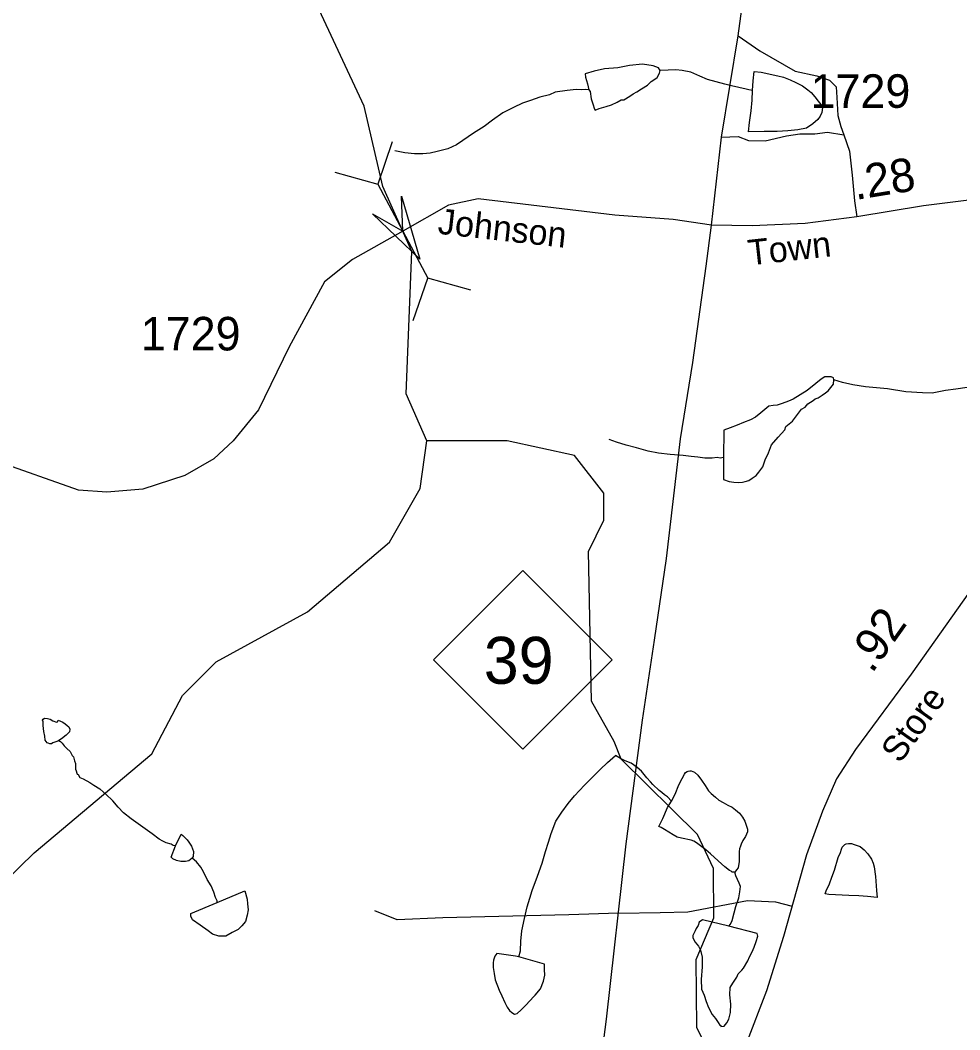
# Model space of a CAD drawing. Extents: x 2126262 to 2293712, y 749403 to 919119.
# Drawn here: x 2215565 to 2219067, y 786501 to 790264 of the extents above; entities that cross this region are included whole.
import ezdxf

# ---------------------------------------------------------------- set-up
doc = ezdxf.new("R2010")
doc.units = 0
for name, color, linetype in [('Exist Hydrographic Creek Single Shore', 7, 'Continuous'), ('Exist Hydrographic Misc Water Feature', 7, 'Continuous'), ('Exist Road Non-System Type 51', 7, 'Continuous'), ('Exist Road Primary NC Attributed', 7, 'Continuous'), ('Exist Road Primary NC Shield CELL', 7, 'Continuous'), ('Exist Road Primary NC Shield Number Label', 7, 'Continuous'), ('Exist Road Secondary Mileage Hundredths English Label', 7, 'Continuous'), ('Exist Road Secondary Structure Pipe CELL', 7, 'Continuous'), ('Exist Road Secondary Structure Standard Bridge Attributed CELL', 7, 'Continuous'), ('Exist Road Secondary Type 51 Attributed', 7, 'Continuous'), ('Exist Road Secondary Type 51 Label', 7, 'Continuous'), ('Exist Road Secondary Type 51 Number Label', 7, 'Continuous')]:
    doc.layers.add(name, color=color, linetype=linetype)

msp = doc.modelspace()

# ---------------------------------------------------------------- linework, layer by layer
at = {"layer": 'Exist Hydrographic Creek Single Shore'}
for points in [[(2217080.2, 788695.4), (2217004.1, 788870.8), (2217025.2, 789401.8), (2216916.1, 789643.5), (2216847.2, 789943.5), (2216661.3, 790340.9), (2216626.2, 790531.9), (2216621.3, 791283.1)], [(2217779.2, 787575.6), (2217695.1, 787725), (2217683.2, 788282.8), (2217740.2, 788399.7), (2217740.2, 788501.4), (2217631.2, 788641.4), (2217380.2, 788695.8), (2217080.2, 788695.4)]]:
    msp.add_lwpolyline(points, dxfattribs=at)
at = {"layer": 'Exist Hydrographic Misc Water Feature'}
for points in [[(2217950.6, 790075.7), (2217944.6, 790085.6), (2217924.5, 790093.5), (2217884.5, 790099.2), (2217836.6, 790094.8), (2217792.5, 790086.5), (2217742.7, 790082.2), (2217704.5, 790074), (2217670.9, 790063.7), (2217672.7, 790051.7), (2217679.1, 790025.8), (2217685, 790003.9)], [(2217685, 790003.9), (2217689.3, 789997.9), (2217693.2, 789969.9), (2217699.6, 789952), (2217705.5, 789932), (2217707.8, 789928), (2217723.6, 789934.2), (2217749.6, 789942.3), (2217769.5, 789948.5), (2217789.6, 789958.6), (2217805.4, 789966.7), (2217815.2, 789966.7), (2217837.4, 789980.9), (2217849.3, 789989), (2217863, 789997.1), (2217881.1, 790007.2), (2217903, 790021.3), (2217916.7, 790035.4), (2217930.9, 790043.5), (2217938.9, 790049.6), (2217948.5, 790065.7), (2217950.6, 790075.7)], [(2218295.1, 790002.1), (2218281.1, 790004), (2218270.9, 790005.9), (2218216.7, 790019.5), (2218190.9, 790025.3), (2218126.9, 790042.9), (2218098.6, 790054.7), (2218064.6, 790070.4), (2218032.6, 790076.2), (2218008.6, 790078), (2217980.5, 790077.9), (2217950.6, 790075.7)], [(2218295.1, 790002.1), (2218296.9, 790038), (2218300.6, 790072), (2218326.6, 790070.2), (2218388.6, 790056.7), (2218410.5, 790050.9), (2218434.5, 790041), (2218456.6, 790031.2), (2218480.8, 790019.3), (2218500.7, 790003.5), (2218512.8, 789993.6), (2218527, 789977.7), (2218539.1, 789961.7), (2218549.3, 789949.8), (2218555.3, 789937.9), (2218553.2, 789919.9), (2218547.5, 789905.8), (2218537.6, 789893.8), (2218519.8, 789877.7), (2218495.8, 789861.5), (2218463.8, 789855.3), (2218426.1, 789851), (2218386.1, 789848.7), (2218338.1, 789848.4), (2218280.1, 789848), (2218283.8, 789882.1), (2218289.5, 789926), (2218293.4, 789966), (2218295.1, 790002.1)], [(2217685, 790003.9), (2217671.1, 790005.8), (2217659, 790003.6), (2217637.1, 790005.5), (2217603.4, 790001.3), (2217559.3, 789995), (2217537.4, 789984.8), (2217501.3, 789976.6), (2217467.7, 789964.3), (2217437.5, 789954.2), (2217403.9, 789937.9), (2217363.9, 789917.7), (2217326, 789891.4), (2217294.4, 789867.2), (2217254.6, 789842.9), (2217214.6, 789814.6), (2217190.9, 789798.5), (2217158.9, 789784.3), (2217119.1, 789774), (2217093, 789767.8), (2217065.2, 789765.6), (2217035, 789765.5), (2216999.1, 789769.2), (2216961, 789776.9)], [(2218598.3, 788922.6), (2218596.3, 788930.6), (2218588.3, 788934.5), (2218578.2, 788934.4), (2218564.3, 788934.3), (2218550.4, 788926.2), (2218530.3, 788910.1), (2218498.5, 788883.9), (2218446.8, 788851.6), (2218428.8, 788843.4), (2218405, 788835.2), (2218387.1, 788829.2), (2218371.1, 788827.1), (2218355.1, 788824.9), (2218341, 788812.9), (2218325.4, 788800.7), (2218305.3, 788784.6), (2218287.3, 788774.5), (2218261.6, 788764.3), (2218237.6, 788754.2), (2218211.6, 788744), (2218187.8, 788735.8), (2218186.4, 788633.9)], [(2218186.4, 788633.9), (2218187, 788551.8), (2218207.1, 788544), (2218225.1, 788542.1), (2218243, 788540.2), (2218257.1, 788542.3), (2218267, 788544.4), (2218281.1, 788548.5), (2218292.8, 788556.6), (2218308.8, 788566.7), (2218318.8, 788578.8), (2218332.6, 788598.8), (2218342.2, 788624.9), (2218354.3, 788651), (2218366, 788681), (2218389.8, 788709.2), (2218415.6, 788737.3), (2218419.5, 788749.4), (2218443.3, 788769.5), (2218477.1, 788813.8), (2218491.1, 788821.8), (2218500.7, 788833.9), (2218520.8, 788846), (2218528.8, 788852.1), (2218538.9, 788856.2), (2218554.7, 788866.3), (2218566.6, 788874.4), (2218576.6, 788882.4), (2218586.6, 788894.5), (2218596.3, 788906.5), (2218598.3, 788922.6)], [(2219094.4, 788894), (2219052.3, 788887.8), (2219014.4, 788883.4), (2218964.6, 788873.1), (2218928.5, 788874.8), (2218866.5, 788878.4), (2218798.3, 788890), (2218716.2, 788897.3), (2218668.3, 788905), (2218630.3, 788912.8), (2218598.3, 788922.6)], [(2214355.2, 785277.7), (2214495.1, 785570), (2214808.2, 786045.8), (2214839.1, 786287.9), (2214971.2, 786531.2), (2215137.1, 786632.8), (2215393.2, 786942.4), (2215617.1, 787160.9), (2216056.1, 787529.1), (2216170.1, 787746.5), (2216295.2, 787871.9), (2216635.2, 788058.4), (2216941.1, 788317.8), (2217056.2, 788518.8), (2217080.2, 788695.4)], [(2218186.4, 788633.9), (2218174.5, 788631.7), (2218162.4, 788633.6), (2218144.6, 788631.5), (2218116.5, 788631.3), (2218090.6, 788635.1), (2218066.6, 788637), (2218036.3, 788640.8), (2217988.3, 788644.5), (2217944.2, 788650.2), (2217906.3, 788657.9), (2217862.4, 788669.6), (2217824.3, 788679.3), (2217788, 788691), (2217760.1, 788700.9)], [(2215708.5, 787579.1), (2215704.6, 787577.1), (2215686.8, 787570.9), (2215680.9, 787566.9), (2215674.9, 787566.9), (2215668.8, 787568.8), (2215664.9, 787570.8), (2215658.5, 787580.8), (2215656.7, 787594.7), (2215652.6, 787612.7), (2215650.3, 787634.7), (2215650.3, 787640.7), (2215650.3, 787648.7), (2215648, 787654.7), (2215650.1, 787658.7), (2215656, 787662.7), (2215666.1, 787660.8), (2215676.1, 787658.9), (2215686, 787652.9), (2215700.1, 787647), (2215704, 787649), (2215706.1, 787655), (2215724.1, 787647.2), (2215732.3, 787641.2), (2215740.3, 787635.3), (2215746.3, 787629.4), (2215750.4, 787621.4), (2215748.3, 787611.4), (2215736.6, 787599.3), (2215718.6, 787585.2), (2215708.5, 787579.1)], [(2215708.5, 787579.1), (2215714.5, 787575.1), (2215720.8, 787569.2), (2215728.8, 787559.2), (2215738.9, 787549.3), (2215750.8, 787537.4), (2215759, 787523.5), (2215763.1, 787517.5), (2215767, 787503.6), (2215771.3, 787493.6), (2215771.3, 787479.6), (2215771.3, 787471.6), (2215773.3, 787465.6), (2215775.6, 787457.6), (2215777.6, 787453.6), (2215781.5, 787451.7), (2215787.5, 787441.7), (2215799.6, 787435.8), (2215823.8, 787421.9), (2215839.8, 787412), (2215861.7, 787398.3), (2215875.9, 787386.3), (2215890, 787372.4), (2215904.2, 787360.5)], [(2218497, 784966.2), (2218211.2, 785378.8), (2218202.2, 785497.1), (2218160.2, 785612.7), (2218240.1, 786037.5), (2218205.1, 786271.1), (2218087.2, 786509.8), (2218085.1, 786762.4), (2218150.1, 786918.4), (2218149.1, 787102.2), (2218090.2, 787228.1), (2217805.2, 787509.4), (2217779.2, 787575.6)], [(2217423.6, 786773.3), (2217429.3, 786795.3), (2217431, 786831.3), (2217434.9, 786869.3), (2217444.5, 786915.3), (2217454.3, 786959.4), (2217464, 786991.4), (2217473.8, 787019.5), (2217493.5, 787073.6), (2217511.1, 787121.7), (2217522.8, 787165.8), (2217534.5, 787199.9), (2217544.4, 787232), (2217562, 787278), (2217583.7, 787312.1), (2217607.5, 787344.3), (2217631.3, 787372.5), (2217669, 787412.7), (2217698.8, 787442.9), (2217726.5, 787471.1), (2217754.3, 787497.2), (2217784.3, 787523.4)], [(2217993.2, 787352.9), (2217977.2, 787368.8), (2217967, 787376.8), (2217957.1, 787384.7), (2217947.1, 787392.6), (2217922.9, 787414.5), (2217914.9, 787424.4), (2217900.7, 787440.3), (2217880.7, 787464.1), (2217864.5, 787478), (2217842.3, 787493.9), (2217820.4, 787503.7), (2217802.3, 787511.6), (2217790.2, 787519.5), (2217784.3, 787523.4)], [(2217993.2, 787352.9), (2217997.3, 787361), (2218009, 787385.1), (2218017, 787407.1), (2218022.8, 787419.1), (2218032.8, 787437.2), (2218040.6, 787453.3), (2218044.5, 787459.3), (2218050.6, 787463.3), (2218054.5, 787465.3), (2218060.5, 787465.4), (2218066.6, 787465.5), (2218072.6, 787463.5), (2218078.5, 787461.5), (2218090.6, 787449.6), (2218104.8, 787431.7), (2218118.7, 787411.8), (2218131, 787391.9), (2218141.1, 787382), (2218157.1, 787368.1), (2218169.4, 787356.2), (2218185.4, 787348.3), (2218203.2, 787338.4), (2218219.4, 787330.5), (2218231.5, 787320.6), (2218245.6, 787308.7), (2218257.5, 787292.8), (2218265.7, 787278.9), (2218275.8, 787249), (2218276, 787239), (2218268, 787220.9), (2218258.4, 787206.8), (2218252.2, 787192.8), (2218250.4, 787184.8), (2218246.5, 787174.8), (2218244.6, 787164.8), (2218244.6, 787158.8), (2218244.6, 787142.8), (2218244.8, 787126.8), (2218242.8, 787112.8), (2218241.1, 787104.8), (2218235, 787096.8), (2218233.1, 787092.7), (2218229, 787088.7)], [(2216143.2, 787186.2), (2216135, 787188.2), (2216127, 787192.1), (2216109, 787198), (2216097.1, 787203.9), (2216083, 787211.8), (2216056.7, 787231.6), (2215978.6, 787287.1), (2215950.3, 787308.9), (2215930.4, 787330.7), (2215910.1, 787354.5), (2215904.2, 787360.5)], [(2218229, 787088.7), (2218223.1, 787088.6), (2218219, 787088.6), (2218215.1, 787092.6), (2218209.1, 787094.6), (2218191.1, 787108.5), (2218166.7, 787130.3), (2218138.6, 787156.1), (2218120.6, 787171.9), (2218086.3, 787197.7), (2218076.3, 787203.6), (2218066.2, 787207.5), (2218030.3, 787215.2), (2218014.3, 787219.1), (2217998.4, 787227.1), (2217966, 787246.8), (2217954.1, 787254.8), (2217946.1, 787258.7), (2217959.8, 787288.8), (2217977.6, 787328.9), (2217993.2, 787352.9)], [(2216143.2, 787186.2), (2216164.8, 787230.4), (2216170.7, 787224.4), (2216181, 787214.5), (2216187.1, 787208.5), (2216193.1, 787200.6), (2216203.1, 787184.7), (2216207.2, 787174.7), (2216211.3, 787164.8), (2216211.3, 787158.8), (2216209.3, 787152.8), (2216209.5, 787146.8), (2216205.6, 787140.7)], [(2216205.6, 787140.7), (2216193.5, 787130.6), (2216181.6, 787128.6), (2216163.5, 787128.4), (2216147.6, 787132.3), (2216133.6, 787138.2), (2216127.5, 787144.2), (2216143.2, 787186.2)], [(2218614.5, 787143.3), (2218622.3, 787161.4), (2218626.2, 787173.4), (2218628.3, 787181.4), (2218638.3, 787191.5), (2218644.1, 787193.5), (2218652.1, 787195.6), (2218664, 787195.7), (2218674, 787191.7), (2218696.4, 787183.9), (2218710.3, 787172), (2218724.2, 787156.1), (2218738.6, 787136.2), (2218744.5, 787122.3), (2218748.8, 787108.3), (2218752.9, 787072.3), (2218757.3, 787020.4), (2218759.5, 786994.4), (2218723.6, 786998.1), (2218691.6, 786999.9), (2218653.5, 787001.6), (2218579.5, 787005.2), (2218565.5, 787007.1), (2218569.2, 787019.1), (2218581.3, 787045.2), (2218591, 787069.2), (2218600.8, 787095.3), (2218614.5, 787143.3)], [(2216298.5, 786975.4), (2216298.5, 786981.4), (2216292.5, 786993.4), (2216286.4, 787013.3), (2216276.1, 787037.3), (2216262, 787061.1), (2216247.8, 787089), (2216237.8, 787106.9), (2216221.6, 787126.8), (2216205.6, 787140.7)], [(2218206.5, 786886.7), (2218212.2, 786894.6), (2218218.4, 786908.7), (2218226, 786936.8), (2218232.1, 786960.8), (2218243.8, 786992.8), (2218247.5, 787014.8), (2218249.3, 787034.9), (2218245.2, 787046.8), (2218233.1, 787074.7), (2218229, 787088.7)], [(2216298.5, 786975.4), (2216402.2, 787018.1), (2216410.6, 786988.2), (2216412.5, 786970.2), (2216414.7, 786948.2), (2216410.8, 786928.2), (2216405.1, 786904.2), (2216391.2, 786888), (2216377.2, 786874), (2216355.3, 786863.8), (2216331.5, 786849.7), (2216305.6, 786849.5), (2216281.2, 786857.3), (2216265.3, 786869.2), (2216235.3, 786891), (2216207, 786910.8), (2216201.1, 786924.7), (2216200.9, 786934.7), (2216298.5, 786975.4)], [(2218206.5, 786886.7), (2218108.3, 786910), (2218096.4, 786901.8), (2218092.5, 786889.8), (2218084.5, 786877.8), (2218080.6, 786869.8), (2218072.8, 786851.7), (2218072.8, 786843.7), (2218080.8, 786827.8), (2218093.1, 786811.9), (2218101.1, 786798), (2218107.2, 786771.9), (2218107.6, 786736), (2218103.7, 786688), (2218104, 786652), (2218114.2, 786630.1), (2218122.2, 786606.1), (2218130.6, 786584.2), (2218144.8, 786558.3), (2218156.9, 786542.4), (2218167.1, 786528.5), (2218173.1, 786518.5), (2218177, 786516.6)], [(2218177, 786516.6), (2218177.2, 786512.5), (2218189.1, 786514.6), (2218199.1, 786526.7), (2218206.9, 786540.8), (2218212.6, 786564.8), (2218214.5, 786596.8), (2218210.4, 786630.7), (2218212, 786658.8), (2218221.9, 786674.8), (2218235.8, 786696.9), (2218241.5, 786709), (2218255.5, 786723), (2218261.6, 786731.1), (2218277.2, 786757.2), (2218283.4, 786773.2), (2218293, 786791.3), (2218301, 786809.3), (2218308.8, 786829.3), (2218314.5, 786849.4), (2218312.5, 786859.4), (2218206.5, 786886.7)], [(2217423.6, 786773.3), (2217411.5, 786775.2), (2217341.6, 786784.7), (2217333.6, 786774.6), (2217329.5, 786760.6), (2217327.8, 786750.7), (2217327.8, 786732.6), (2217332.1, 786710.6), (2217336, 786686.7), (2217350.4, 786648.8), (2217360.6, 786626.9), (2217370.9, 786603), (2217380.7, 786585), (2217389.1, 786573.1), (2217397.1, 786565.1), (2217407, 786559.2), (2217417, 786561.3), (2217432.8, 786575.4), (2217448.8, 786591.5), (2217466.4, 786609.6), (2217478.5, 786623.7), (2217484.5, 786629.8), (2217504.4, 786653.9), (2217516.1, 786682), (2217520, 786704), (2217519.8, 786725.9), (2217519.8, 786745.9), (2217423.6, 786773.3)]]:
    msp.add_lwpolyline(points, dxfattribs=at)
at = {"layer": 'Exist Road Non-System Type 51'}
for points in [[(2218241.5, 790205.8), (2218321.9, 790149), (2218453.1, 790073.5), (2218534.1, 790056.8), (2218581.5, 790040), (2218606.6, 790014.9), (2218609.4, 789975.7), (2218612.2, 789908.7), (2218623.4, 789866.8), (2218634.5, 789836.1)], [(2218179.4, 789827.9), (2218241.7, 789829.8), (2218279.4, 789815.8), (2218342.2, 789814.4), (2218421.7, 789832.6), (2218470.6, 789839.6), (2218526.4, 789839.6), (2218573.8, 789846.5), (2218634.5, 789836.1)], [(2218634.5, 789836.1), (2218656.2, 789775.3), (2218665.9, 789685.9), (2218674.3, 789590.9), (2218684.1, 789530.9)], [(2217794.9, 786935.8), (2217950, 786938.1), (2218053.3, 786940.9), (2218276.6, 786982.8), (2218379.8, 786977.2), (2218441.9, 786961.1)], [(2217794.9, 786935.8), (2217609.4, 786929.7), (2217140.5, 786918.5), (2216970.2, 786910.1), (2216886.5, 786943.7)]]:
    msp.add_lwpolyline(points, dxfattribs=at)
at = {"layer": 'Exist Road Primary NC Attributed'}
for points in [[(2218141.2, 789499.3), (2218179.4, 789827.9), (2218241.5, 790205.8), (2218293.9, 790590.6), (2218353.2, 791043.9), (2218383.9, 791246.4), (2218420.9, 791516.7), (2218481.6, 792023), (2218509.5, 792239.6), (2218535.1, 792454.9)], [(2217547.2, 785067.5), (2217573, 785245.6), (2217632.3, 785691.9), (2217656.1, 785859.5), (2217681.2, 786049.5), (2217716.8, 786280.7), (2217750.3, 786540.5), (2217823.5, 787193.5), (2217884.2, 787655.1), (2217929.6, 787953.4), (2217974.3, 788257.9), (2218025.9, 788703.5), (2218072.6, 788987.7), (2218121.5, 789346.7), (2218141.2, 789499.3)]]:
    msp.add_lwpolyline(points, dxfattribs=at)
at = {"layer": 'Exist Road Primary NC Shield CELL'}
msp.add_lwpolyline([(2217105.8, 787880), (2217438.8, 788213), (2217771.8, 787880), (2217438.8, 787547)], close=True, dxfattribs=at)
at = {"layer": 'Exist Road Secondary Structure Pipe CELL'}
for p, q in [((2216951.9, 789810.6), (2216898.5, 789652.8)), ((2216738, 789697.6), (2216898.5, 789652.8)), ((2216898.5, 789652.8), (2217083.8, 789302)), ((2217030.3, 789144.2), (2217083.8, 789302)), ((2217244.2, 789257.2), (2217083.8, 789302))]:
    msp.add_line(p, q, dxfattribs=at)
at = {"layer": 'Exist Road Secondary Structure Standard Bridge Attributed CELL'}
msp.add_lwpolyline([(2216986.7, 789607.3), (2217054, 789372.9), (2216878.5, 789542.2), (2216991.1, 789477.4)], close=True, dxfattribs=at)
at = {"layer": 'Exist Road Secondary Type 51 Attributed'}
for points in [[(2218141.2, 789499.3), (2217999.2, 789521.3), (2217781.5, 789536.7), (2217271.4, 789597.4), (2217161.1, 789573.7), (2216991.1, 789477.4)], [(2219634.1, 789626.5), (2219392.6, 789619.5), (2219140.7, 789597.9), (2218932.7, 789571.3), (2218684.1, 789530.9), (2218491, 789506.4), (2218292.8, 789496.6), (2218141.2, 789499.3)], [(2216991.1, 789477.4), (2216804.1, 789371.4), (2216699.4, 789289), (2216567.5, 789046.7), (2216453.1, 788812), (2216358.9, 788695.4), (2216286.3, 788628.3), (2216178.8, 788566.9), (2216021.8, 788515.9), (2215887.8, 788504.7), (2215781.8, 788511.7), (2215472, 788620.7)], [(2219906.2, 789281.5), (2219813.3, 789134.6), (2218885.9, 787826.4), (2218678, 787545.6), (2218607.5, 787436), (2218555.8, 787315.8), (2218496.5, 787153.1), (2218410.7, 786847.9), (2218346.5, 786645.4), (2218268.3, 786442.8), (2218168.5, 786263.3), (2218000.4, 785903.6), (2217944.5, 785790.5), (2217839.2, 785556.5), (2217680, 785274.3), (2217547.2, 785067.5)]]:
    msp.add_lwpolyline(points, dxfattribs=at)

# ---------------------------------------------------------------- texts
at = {"layer": 'Exist Road Primary NC Shield Number Label'}
msp.add_text('39', height=175, dxfattribs=at).set_placement((2217292.9, 787790.3))
at = {"layer": 'Exist Road Secondary Mileage Hundredths English Label'}
for s, rotation, p in [('.28', 9.25, (2218678.9, 789593.3)), ('.92', 54.6652, (2218739.9, 787825.8))]:
    msp.add_text(s, height=125, rotation=rotation, dxfattribs=at).set_placement(p)
at = {"layer": 'Exist Road Secondary Type 51 Label'}
for s, rotation, p in [('Johnson', 353.659, (2217118.8, 789468.1)), ('Town', 6.3526, (2218282.9, 789349.5)), ('Store', 54.7247, (2218844.8, 787489.8))]:
    msp.add_text(s, height=95, rotation=rotation, dxfattribs=at).set_placement(p)
at = {"layer": 'Exist Road Secondary Type 51 Number Label'}
for p in [(2218511.1, 789936.9), (2216014.4, 789032.8)]:
    msp.add_text('1729', height=125, dxfattribs=at).set_placement(p)

doc.saveas('drawing.dxf')
